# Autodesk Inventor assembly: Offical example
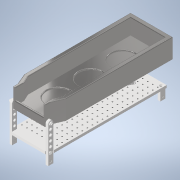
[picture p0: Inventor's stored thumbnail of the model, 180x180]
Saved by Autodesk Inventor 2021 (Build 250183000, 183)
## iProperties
Created: 2020-12
Part Number: Offical example
Document SubType Name: Assembly
Designer: bestm
Author: bestm
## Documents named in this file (12)
- C:\Users\Owner\Desktop\Team48_P3_Milestone4 (Modelling)\Offical example.iam
- C:\Users\Owner\Desktop\Team48_P3_Milestone4 (Modelling)\Stepper Motor Housing.ipt
- C:\Users\Owner\Desktop\Team48_P3_Milestone4 (Modelling)\Stepper Motor Axle.ipt
- C:\Users\Owner\Desktop\Team48_P3_Milestone4 (Modelling)\Mounting Platform.iam
- C:\Users\Owner\Desktop\Team48_P3_Milestone4 (Modelling)\Offical crank.ipt
- C:\Users\Owner\Desktop\Team48_P3_Milestone4 (Modelling)\Part6.ipt
- C:\Users\Owner\Desktop\Team48_P3_Milestone4 (Modelling)\Offical rod #2 conecting plate to rode #1.ipt
- C:\Users\Owner\Desktop\Team48_P3_Milestone4 (Modelling)\Offical plate support.ipt
- C:\Users\Owner\Desktop\Team48_P3_Milestone4 (Modelling)\Offical hopper.ipt
- C:\Users\Owner\Desktop\Team48_P3_Milestone4 (Modelling)\Part5.ipt
- C:\Users\Owner\Desktop\Team48_P3_Milestone4 (Modelling)\O-ring.ipt
- C:\Users\Owner\Desktop\Team48_P3_Milestone4 (Modelling)\Short Screw (Stepper Motor & Linear Actuator).ipt
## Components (14 placed, 11 different names)
1. Stepper Motor Housing:1 — Mate:1, Mate:2, Mate:3, Mate:4, Mate:5, Mate:6, Mate:25, Mate:26, Mate:27, Mate:28, Mate:29, Mate:30, Angle:5, Angle:6
2. Stepper Motor Axle:1 — Mate:1, Mate:2, Mate:7, Angle:1, Mate:8
3. Mounting Platform:2 [sub-assembly] — Mate:3, Mate:4, Mate:5, Mate:6, Mate:16, Angle:2, Mate:22, Mate:24
4. Offical crank:1 — Mate:7, Angle:1, Mate:8, Mate:9, Mate:10
5. Part6:1 — Mate:9, Mate:10, Mate:11, Mate:12, Angle:3, Angle:4
6. Offical rod #2 conecting plate to rode #1:1 — Mate:11, Mate:12, Mate:14, Angle:3, Mate:20
7. Offical plate support:2 — Mate:14, Mate:18, Angle:4, Mate:20
8. Offical hopper:1 — Mate:15, Angle:2, Mate:18, Mate:19
9. Part5:1 — Mate:15, Mate:16, Mate:19, Mate:21, Mate:23
10. O-ring:1 — Mate:23, Mate:24
11. O-ring:2 — Mate:21, Mate:22
12. Short Screw (Stepper Motor & Linear Actuator):1 — Mate:27, Mate:30, Angle:6, Angle:7
13. Short Screw (Stepper Motor & Linear Actuator):2 — Mate:26, Mate:29, Angle:5
14. Short Screw (Stepper Motor & Linear Actuator):3 — Mate:25, Mate:28, Angle:7
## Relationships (35: Mate 28, Angle 7)
- Mate:1: Stepper Motor Housing:1 ↔ Stepper Motor Axle:1
- Mate:2: Stepper Motor Housing:1 ↔ Stepper Motor Axle:1
- Mate:3: Stepper Motor Housing:1 ↔ Mounting Platform:2
- Mate:4: Stepper Motor Housing:1 ↔ Mounting Platform:2
- Mate:5: Stepper Motor Housing:1 ↔ Mounting Platform:2
- Mate:6: Stepper Motor Housing:1 ↔ Mounting Platform:2
- Mate:7: Stepper Motor Axle:1 ↔ Offical crank:1
- Angle:1: Stepper Motor Axle:1 ↔ Offical crank:1
- Mate:8: Stepper Motor Axle:1 ↔ Offical crank:1
- Mate:9: Offical crank:1 ↔ Part6:1
- Mate:10: Offical crank:1 ↔ Part6:1
- Mate:11: Part6:1 ↔ Offical rod #2 conecting plate to rode #1:1
- Mate:12: Part6:1 ↔ Offical rod #2 conecting plate to rode #1:1
- Mate:14: Offical rod #2 conecting plate to rode #1:1 ↔ Offical plate support:2
- Mate:15: Offical hopper:1 ↔ Part5:1
- Mate:16: Mounting Platform:2 ↔ Part5:1
- Angle:2: Mounting Platform:2 ↔ Offical hopper:1
- Mate:18: Offical plate support:2 ↔ Offical hopper:1
- Mate:19: Offical hopper:1 ↔ Part5:1
- Angle:3: Part6:1 ↔ Offical rod #2 conecting plate to rode #1:1
- Angle:4: Part6:1 ↔ Offical plate support:2
- Mate:20: Offical rod #2 conecting plate to rode #1:1 ↔ Offical plate support:2
- Mate:21: Part5:1 ↔ O-ring:2
- Mate:22: Mounting Platform:2 ↔ O-ring:2
- Mate:23: Part5:1 ↔ O-ring:1
- Mate:24: Mounting Platform:2 ↔ O-ring:1
- Mate:25: Stepper Motor Housing:1 ↔ Short Screw (Stepper Motor & Linear Actuator):3
- Mate:26: Stepper Motor Housing:1 ↔ Short Screw (Stepper Motor & Linear Actuator):2
- Mate:27: Stepper Motor Housing:1 ↔ Short Screw (Stepper Motor & Linear Actuator):1
- Mate:28: Stepper Motor Housing:1 ↔ Short Screw (Stepper Motor & Linear Actuator):3
- Mate:29: Stepper Motor Housing:1 ↔ Short Screw (Stepper Motor & Linear Actuator):2
- Mate:30: Stepper Motor Housing:1 ↔ Short Screw (Stepper Motor & Linear Actuator):1
- Angle:5: Stepper Motor Housing:1 ↔ Short Screw (Stepper Motor & Linear Actuator):2
- Angle:6: Stepper Motor Housing:1 ↔ Short Screw (Stepper Motor & Linear Actuator):1
- Angle:7: Short Screw (Stepper Motor & Linear Actuator):1 ↔ Short Screw (Stepper Motor & Linear Actuator):3
